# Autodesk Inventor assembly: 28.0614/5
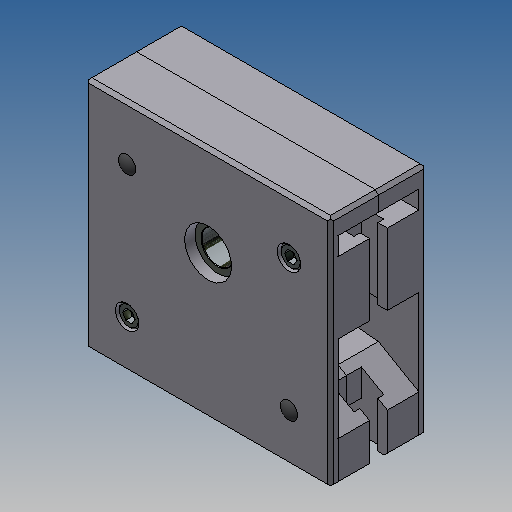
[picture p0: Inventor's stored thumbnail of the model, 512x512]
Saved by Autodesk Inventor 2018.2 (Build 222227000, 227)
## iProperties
Created: 2018-05
Part Number: 28.0614/5
Document SubType Name: Assembly
Designer: amoles
Description: TIMING BELT PULLEY T45 15mm
Stock Number: 28.0614 TIMING BELT PULLEY T45
Author: amoles
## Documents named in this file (12)
- Y:\INVENTOR LIBRARIES\PARTS LIBRARY\READY FOR USE MODULES LR\28.0614_5 TIMING BELT PULLEY T45 15mm.iam
- Y:\INVENTOR LIBRARIES\PARTS LIBRARY\READY FOR USE MODULES LR\SUBCOMPONENTS\28.0614 TIMING BELT PULLEY T45 RIGHT PLATE.ipt
- Y:\INVENTOR LIBRARIES\PARTS LIBRARY\READY FOR USE MODULES LR\SUBCOMPONENTS\SHIM DIN 988 - 25 x 35 x 0,1.ipt
- 00005263.ipt
- Y:\INVENTOR LIBRARIES\PARTS LIBRARY\READY FOR USE MODULES LR\Subcomponents\28.0083 BEARING.ipt
- Y:\INVENTOR LIBRARIES\PARTS LIBRARY\READY FOR USE MODULES LR\SUBCOMPONENTS\SHIM DIN 988 - 37 x 47 x 0,1.ipt
- 00005262.ipt
- Y:\INVENTOR LIBRARIES\PARTS LIBRARY\READY FOR USE MODULES LR\SUBCOMPONENTS\28.0614 TIMING BELT PULLEY T45 LEFT PLATE.ipt
- Y:\INVENTOR LIBRARIES\PARTS LIBRARY\FASTENING ELEMENTS\SCREWS CAP\M6X30 HIGH HEAD.ipt
- 00005264.ipt
- Y:\INVENTOR LIBRARIES\PARTS LIBRARY\END CAPS\22.1203 HOLE CAP M6.ipt
- Y:\INVENTOR LIBRARIES\PARTS LIBRARY\READY FOR USE MODULES LR\SUBCOMPONENTS\28.0047_4 T45 PULLEY 15mm.ipt
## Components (17 placed, 8 different names)
1. 28.0614 TIMING BELT PULLEY T45 RIGHT PLATE:1 — Flush:1, Flush:2, Flush:3, Mate:5, Mate:6, Mate:7, Angle:1, Insert:7, Insert:8, Insert:11, Insert:12, Angle:2
2. 28.0047_4 T45 PULLEY 15mm:1 — Insert:1, Insert:2, Mate:1, Mate:3, Mate:5, Mate:6, Mate:8, Angle:2
3. 00005263:1 — Insert:1, Insert:3
4. 00005263:2 — Insert:2, Insert:4
5. 28.0083 BEARING:1 — Insert:4, Mate:4
6. 28.0083 BEARING:2 — Insert:3, Mate:2
7. 00005262:1 — Mate:1, Mate:2
8. 00005262:2 — Mate:3, Mate:4
9. 28.0614 TIMING BELT PULLEY T45 LEFT PLATE:1 — Mate:7, Mate:8, Angle:1, Insert:5, Insert:6, Insert:9, Insert:10
10. 00005264:1 — Insert:6
11. 00005264:2 — Insert:5
12. 00005264:3 — Insert:8
13. 00005264:4 — Insert:7
14. 22.1203 HOLE CAP M6:1 — Insert:9
15. 22.1203 HOLE CAP M6:2 — Insert:10
16. 22.1203 HOLE CAP M6:3 — Insert:12
17. 22.1203 HOLE CAP M6:4 — Insert:11
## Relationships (25: Insert 12, Mate 8, Flush 3, Angle 2)
- Flush:1: 28.0614 TIMING BELT PULLEY T45 RIGHT PLATE:1
- Flush:2: 28.0614 TIMING BELT PULLEY T45 RIGHT PLATE:1
- Flush:3: 28.0614 TIMING BELT PULLEY T45 RIGHT PLATE:1
- Insert:1: 28.0047_4 T45 PULLEY 15mm:1 ↔ 00005263:1
- Insert:2: 28.0047_4 T45 PULLEY 15mm:1 ↔ 00005263:2
- Insert:3: 00005263:1 ↔ 28.0083 BEARING:2
- Insert:4: 00005263:2 ↔ 28.0083 BEARING:1
- Mate:1: 28.0047_4 T45 PULLEY 15mm:1 ↔ 00005262:1
- Mate:2: 28.0083 BEARING:2 ↔ 00005262:1
- Mate:3: 28.0047_4 T45 PULLEY 15mm:1 ↔ 00005262:2
- Mate:4: 28.0083 BEARING:1 ↔ 00005262:2
- Mate:5: 28.0614 TIMING BELT PULLEY T45 RIGHT PLATE:1 ↔ 28.0047_4 T45 PULLEY 15mm:1
- Mate:6: 28.0614 TIMING BELT PULLEY T45 RIGHT PLATE:1 ↔ 28.0047_4 T45 PULLEY 15mm:1
- Mate:7: 28.0614 TIMING BELT PULLEY T45 RIGHT PLATE:1 ↔ 28.0614 TIMING BELT PULLEY T45 LEFT PLATE:1
- Mate:8: 28.0047_4 T45 PULLEY 15mm:1 ↔ 28.0614 TIMING BELT PULLEY T45 LEFT PLATE:1
- Angle:1: 28.0614 TIMING BELT PULLEY T45 RIGHT PLATE:1 ↔ 28.0614 TIMING BELT PULLEY T45 LEFT PLATE:1
- Insert:5: 28.0614 TIMING BELT PULLEY T45 LEFT PLATE:1 ↔ 00005264:2
- Insert:6: 28.0614 TIMING BELT PULLEY T45 LEFT PLATE:1 ↔ 00005264:1
- Insert:7: 28.0614 TIMING BELT PULLEY T45 RIGHT PLATE:1 ↔ 00005264:4
- Insert:8: 28.0614 TIMING BELT PULLEY T45 RIGHT PLATE:1 ↔ 00005264:3
- Insert:9: 28.0614 TIMING BELT PULLEY T45 LEFT PLATE:1 ↔ 22.1203 HOLE CAP M6:1
- Insert:10: 28.0614 TIMING BELT PULLEY T45 LEFT PLATE:1 ↔ 22.1203 HOLE CAP M6:2
- Insert:11: 28.0614 TIMING BELT PULLEY T45 RIGHT PLATE:1 ↔ 22.1203 HOLE CAP M6:4
- Insert:12: 28.0614 TIMING BELT PULLEY T45 RIGHT PLATE:1 ↔ 22.1203 HOLE CAP M6:3
- Angle:2: 28.0614 TIMING BELT PULLEY T45 RIGHT PLATE:1 ↔ 28.0047_4 T45 PULLEY 15mm:1
